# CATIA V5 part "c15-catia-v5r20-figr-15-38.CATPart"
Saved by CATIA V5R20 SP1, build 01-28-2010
Part number: Part1
Bounding box of the stored display mesh (mm): x -63.331 to 99.803, y -39.139 to 39.139, z 0 to 68.615
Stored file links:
  D:\v5_r20\psrt_files_downloaded\c15\c15-catia-v5r20-figr-15-38.CATPart
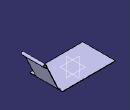
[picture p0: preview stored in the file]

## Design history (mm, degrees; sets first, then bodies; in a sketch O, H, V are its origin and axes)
SheetMetalParameters1: Thickness 1, BendRadius 2, KFactor 0.400515 {= log(min(100,max(20*SheetMetalParameters1.BendRadius,SheetMetalParameters1.Thickness)/SheetMetalParameters1.Thickness))/log(100)/2}, ReliefRadialLength 1, ReliefAxialLength 2, MinimumBendRadius 0
Body1 (main body)
  Sketch1 on xy-plane, origin (0, 0, 0), H (1, 0, 0), V (0, 1, 0)
    line L1 (-63.3311, 39.1393) -> (63.3311, 39.1393)
    line L2 (63.3311, 39.1393) -> (63.3311, -39.1393)
    line L3 (63.3311, -39.1393) -> (-63.3311, -39.1393)
    line L4 (-63.3311, -39.1393) -> (-63.3311, 39.1393)
    horizontal: L1 H, L3 H
    vertical: L2 V, L4 V
    symmetry: L4 L2 V, L1 L3 H
  Wall1: Thickness 1, Profile Sketch1
  d_NewWallOnEdge1: NewWallOnEdge_Edge edge [face of Wall1 | face of Wall1], NewWallOnEdge_Length 67, NewWallOnEdge_HeightLimitOffset 0, NewWallOnEdge_WidthOffset1 -16, NewWallOnEdge_WidthOffset2 -9, NewWallOnEdge_Angle 115, NewWallOnEdge_BendRadiusValue 2 {= SheetMetalParameters1.BendRadius}, NewWallOnEdge_BendTable SheetMetalParameters1, KFacteur 0.400515 {= log(min(100,max(20*d_NewWallOnEdge1.Radius,SheetMetalParameters1.Thickness)/SheetMetalParameters1.Thickness))/log(100)/2}
  Flange1: Angle 22.6199 {= 2*atan(Flange1.Radius/Flange1.Length)}, Length 10, Radius 2, KFacteur 0.400515 {= log(min(100,max(20*Flange1.Radius,SheetMetalParameters1.Thickness)/SheetMetalParameters1.Thickness))/log(100)/2}, Guide edge [face of d_NewWallOnEdge1 | face of d_NewWallOnEdge1]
